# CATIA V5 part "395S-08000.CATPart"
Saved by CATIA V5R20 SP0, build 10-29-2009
Part number: 395S-08000
Bounding box of the stored display mesh (mm): x -94 to 94, y -62.399 to 227.5, z -62.5 to 62.399
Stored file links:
  C:\Users\Utente\Desktop\3D files 395S\395S-08000.CATPart
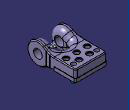
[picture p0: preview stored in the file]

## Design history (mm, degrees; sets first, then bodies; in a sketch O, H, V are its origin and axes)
Set1
  Line1 to Line3: stored without definition
  Point1 "Punto.4": stored without definition
  DatumSurface1 to DatumSurface119 "PartBody"
  DatumSurface120 to DatumSurface139 "SPINE"
Body1 (main body)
